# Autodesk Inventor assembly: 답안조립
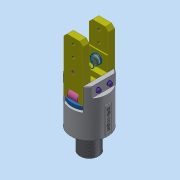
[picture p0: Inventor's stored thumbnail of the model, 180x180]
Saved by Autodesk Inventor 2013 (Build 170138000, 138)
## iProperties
Created: 2019-02
Part Number: 답안조립
Document SubType Name: Assembly
Designer: Administrator
Author: Administrator
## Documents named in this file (11)
- C:\Users\Administrator\Desktop\490207V1014\답안조립.iam
- C:\Users\Administrator\Desktop\490207V1014\본체.ipt
- C:\Users\Administrator\Desktop\490207V1014\E-링.ipt
- C:\Users\Administrator\Desktop\490207V1014\O-링.ipt
- C:\Users\Administrator\Desktop\490207V1014\가이드핀.ipt
- C:\Users\Administrator\Desktop\490207V1014\부시.ipt
- C:\Users\Administrator\Desktop\490207V1014\스프링.ipt
- C:\Users\Administrator\Desktop\490207V1014\평행핀 6x28.ipt
- C:\Users\Administrator\Desktop\490207V1014\피스톤.ipt
- C:\Users\Administrator\Desktop\490207V1014\핀.ipt
- C:\Users\Administrator\Desktop\490207V1014\핑거.ipt
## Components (13 placed, 6 different names)
1. E-링:1
2. O-링:1
3. 가이드핀:1
4. 피스톤:1
5. 핀:1
6. 핑거:1
7. O-링:2
8. 핑거:2
9. 가이드핀:2
10. 핀:2
11. E-링:2
12. E-링:3
13. E-링:4
